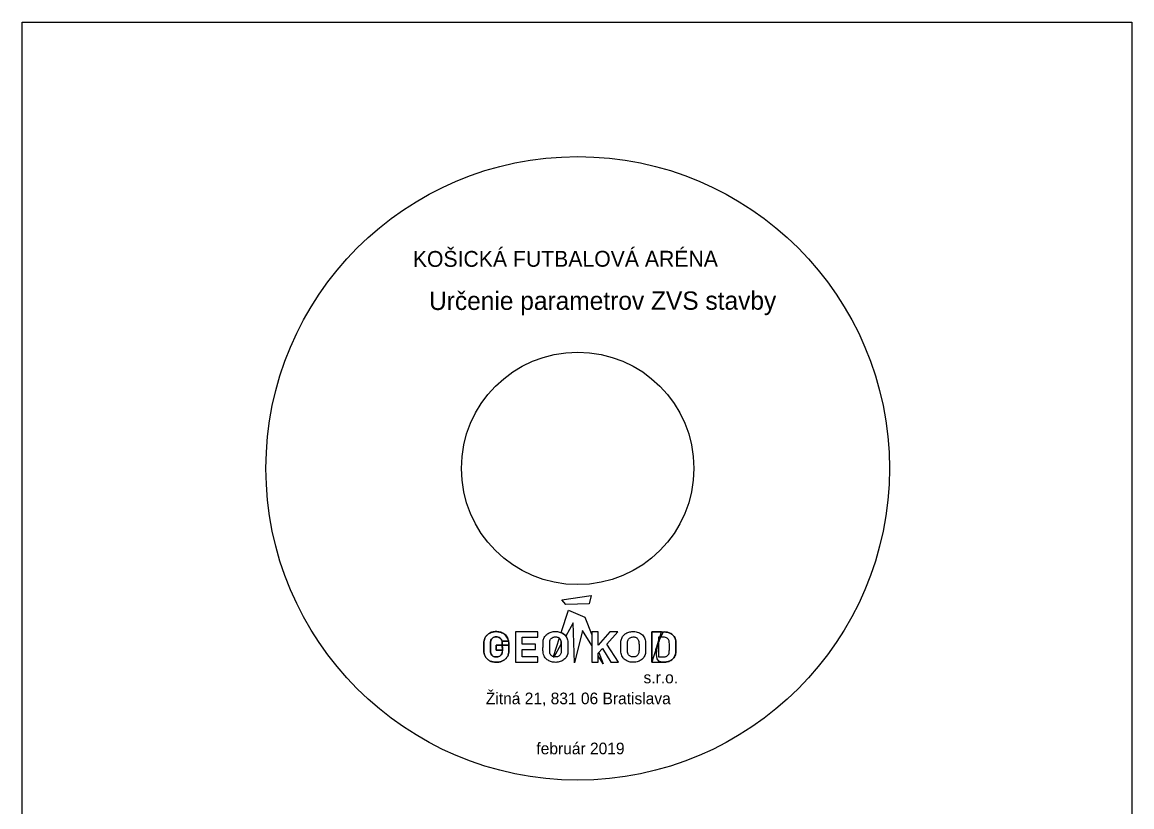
# Model space of a CAD drawing. Extents: x -505246 to -505036, y -1268489 to -1268192.
# Drawn here: x -505246.3 to -505036.3, y -1268340.7 to -1268192.2 of the extents above; entities that cross this region are included whole.
import ezdxf

# ---------------------------------------------------------------- set-up
doc = ezdxf.new("R2010")
doc.units = 0
for name, color, linetype in [('CD_KRUHY', 7, 'Continuous'), ('CD_POPIS', 7, 'Continuous'), ('RAM_NA_TLAC_A4', 7, 'Continuous')]:
    doc.layers.add(name, color=color, linetype=linetype)

msp = doc.modelspace()

# ---------------------------------------------------------------- linework, layer by layer
at = {"layer": 'CD_KRUHY'}
for radius in [59, 22]:
    msp.add_circle((-505141.22, -1268276.61), radius, dxfattribs=at)
at = {"layer": 'CD_POPIS'}
for p, q in [((-505144.36, -1268307.68), (-505142.96, -1268303.45)), ((-505142.96, -1268303.45), (-505139.85, -1268304.76)), ((-505139.85, -1268304.76), (-505138.54, -1268308.11)), ((-505145.5, -1268307.48), (-505145.4, -1268307.48)), ((-505142.07, -1268305.85), (-505143.47, -1268308.35)), ((-505141.8, -1268313.41), (-505142.07, -1268305.85)), ((-505140.31, -1268307.29), (-505141.8, -1268313.41)), ((-505138.54, -1268310.14), (-505140.31, -1268307.29)), ((-505137.32, -1268307.55), (-505138.54, -1268307.55)), ((-505135.12, -1268307.55), (-505137.32, -1268310.05)), ((-505137.32, -1268310.05), (-505137.32, -1268307.55)), ((-505135.7, -1268309.85), (-505133.6, -1268307.55)), ((-505133.6, -1268307.55), (-505135.12, -1268307.55)), ((-505127.18, -1268307.57), (-505125.35, -1268307.57)), ((-505127.18, -1268313.27), (-505127.18, -1268307.57)), ((-505127.18, -1268307.57), (-505127.18, -1268313.27)), ((-505125.35, -1268307.57), (-505127.18, -1268307.57)), ((-505154.25, -1268309.32), (-505155.51, -1268309.32)), ((-505155.51, -1268309.32), (-505154.25, -1268309.32)), ((-505144.71, -1268308.73), (-505145.87, -1268312.25)), ((-505145.48, -1268308.5), (-505145.41, -1268308.5)), ((-505145.48, -1268308.5), (-505145.41, -1268308.5)), ((-505138.54, -1268308.11), (-505138.54, -1268310.14)), ((-505125.93, -1268308.56), (-505125.93, -1268312.28)), ((-505125.93, -1268308.56), (-505125.93, -1268312.28)), ((-505137.22, -1268311.46), (-505136.37, -1268313.63)), ((-505133.49, -1268313.27), (-505135.7, -1268309.85)), ((-505136.37, -1268313.63), (-505137.32, -1268312.1)), ((-505134.93, -1268313.27), (-505133.49, -1268313.27))]:
    msp.add_line(p, q, dxfattribs=at)
for points in [[(-505144.2, -1268301.48), (-505138.67, -1268300.68), (-505139.06, -1268302.26), (-505143.47, -1268302.4)], [(-505152.99, -1268307.53), (-505152.99, -1268313.27), (-505148.78, -1268313.27), (-505148.78, -1268312.26), (-505151.73, -1268312.26), (-505151.73, -1268310.88), (-505149.21, -1268310.88), (-505149.21, -1268309.88), (-505151.73, -1268309.88), (-505151.73, -1268308.54), (-505148.78, -1268308.54), (-505148.78, -1268307.53)]]:
    msp.add_lwpolyline(points, close=True, dxfattribs=at)
for points in [[(-505138.54, -1268307.55), (-505138.54, -1268313.27), (-505137.32, -1268313.27), (-505137.32, -1268311.56), (-505136.51, -1268310.7), (-505134.93, -1268313.27)], [(-505144.33, -1268309.9), (-505144.33, -1268309.77), (-505144.34, -1268309.61), (-505144.35, -1268309.47), (-505144.37, -1268309.33), (-505144.41, -1268309.21), (-505144.46, -1268309.06), (-505144.53, -1268308.93), (-505144.62, -1268308.82), (-505144.71, -1268308.73)], [(-505143.47, -1268308.35), (-505143.51, -1268308.3), (-505143.58, -1268308.22), (-505143.65, -1268308.15), (-505143.74, -1268308.07), (-505143.82, -1268308), (-505143.91, -1268307.94), (-505143.99, -1268307.88), (-505144.08, -1268307.83), (-505144.18, -1268307.77), (-505144.27, -1268307.72), (-505144.36, -1268307.68)], [(-505155.47, -1268311.01), (-505156.67, -1268311.01), (-505156.67, -1268310.07), (-505154.23, -1268310.07)], [(-505154.23, -1268310.07), (-505156.67, -1268310.07), (-505156.67, -1268311.01), (-505155.47, -1268311.01)], [(-505145.68, -1268312.3), (-505144.33, -1268309.9)], [(-505137.32, -1268312.1), (-505137.32, -1268311.56), (-505137.22, -1268311.46)], [(-505145.87, -1268312.25), (-505145.84, -1268312.26), (-505145.8, -1268312.28), (-505145.77, -1268312.29), (-505145.73, -1268312.29), (-505145.7, -1268312.3), (-505145.68, -1268312.3)]]:
    msp.add_lwpolyline(points, dxfattribs=at)
for points in [[(-505154.23, -1268310.07), (-505154.23, -1268310.79), (-505154.25, -1268311.44), (-505154.38, -1268312.02), (-505154.66, -1268312.48), (-505155.08, -1268312.87), (-505155.53, -1268313.13), (-505156.12, -1268313.28), (-505156.66, -1268313.32), (-505157.22, -1268313.28), (-505157.78, -1268313.1), (-505158.26, -1268312.78), (-505158.63, -1268312.41), (-505158.88, -1268311.91), (-505158.99, -1268311.35), (-505159.01, -1268310.98), (-505159.01, -1268309.84), (-505158.97, -1268309.23), (-505158.8, -1268308.71), (-505158.52, -1268308.26), (-505157.97, -1268307.82), (-505157.37, -1268307.56), (-505156.68, -1268307.48), (-505155.96, -1268307.54), (-505155.19, -1268307.85), (-505154.6, -1268308.41), (-505154.25, -1268309.32), (-505154.23, -1268310.07), (-505154.25, -1268309.32)], [(-505154.25, -1268309.32), (-505154.6, -1268308.41), (-505155.19, -1268307.85), (-505155.96, -1268307.54), (-505156.68, -1268307.48), (-505157.37, -1268307.56), (-505157.97, -1268307.82), (-505158.52, -1268308.26), (-505158.8, -1268308.71), (-505158.97, -1268309.23), (-505159.01, -1268309.84), (-505159.01, -1268310.98), (-505158.99, -1268311.35), (-505158.88, -1268311.91), (-505158.63, -1268312.41), (-505158.26, -1268312.78), (-505157.78, -1268313.1), (-505157.22, -1268313.28), (-505156.66, -1268313.32), (-505156.12, -1268313.28), (-505155.53, -1268313.13), (-505155.08, -1268312.87), (-505154.66, -1268312.48), (-505154.38, -1268312.02), (-505154.25, -1268311.44), (-505154.23, -1268310.79), (-505154.23, -1268310.07), (-505154.25, -1268309.32), (-505154.23, -1268310.07)], [(-505145.4, -1268307.48), (-505145.37, -1268307.48), (-505145.2, -1268307.47), (-505144.88, -1268307.55), (-505144.45, -1268307.63), (-505144.04, -1268307.85), (-505143.67, -1268308.11), (-505143.37, -1268308.46), (-505143.19, -1268308.86), (-505143.08, -1268309.3), (-505143.08, -1268309.99), (-505143.06, -1268310.71), (-505143.08, -1268311.41), (-505143.14, -1268311.85), (-505143.31, -1268312.22), (-505143.52, -1268312.54), (-505143.81, -1268312.79), (-505144.12, -1268313.02), (-505144.5, -1268313.18), (-505144.92, -1268313.3), (-505145.38, -1268313.33), (-505145.81, -1268313.3), (-505146.19, -1268313.27), (-505146.51, -1268313.12), (-505146.82, -1268312.94), (-505147.12, -1268312.75), (-505147.39, -1268312.47), (-505147.6, -1268312.09), (-505147.75, -1268311.64), (-505147.82, -1268310.89), (-505147.75, -1268310.2), (-505147.79, -1268309.53), (-505147.73, -1268309.15), (-505147.64, -1268308.77), (-505147.46, -1268308.44), (-505147.22, -1268308.17), (-505146.96, -1268307.93), (-505146.63, -1268307.75), (-505146.26, -1268307.58), (-505145.87, -1268307.5), (-505145.61, -1268307.49), (-505145.5, -1268307.48)], [(-505130.68, -1268307.48), (-505131.11, -1268307.51), (-505131.56, -1268307.6), (-505131.93, -1268307.76), (-505132.23, -1268307.94), (-505132.5, -1268308.17), (-505132.72, -1268308.44), (-505132.91, -1268308.78), (-505133.01, -1268309.15), (-505133.06, -1268309.51), (-505133.05, -1268309.92), (-505133.07, -1268311.15), (-505133.02, -1268311.61), (-505132.85, -1268312.12), (-505132.64, -1268312.48), (-505132.41, -1268312.72), (-505132.09, -1268312.95), (-505131.79, -1268313.11), (-505131.48, -1268313.24), (-505131.1, -1268313.3), (-505130.69, -1268313.32), (-505130.2, -1268313.28), (-505129.76, -1268313.16), (-505129.42, -1268313.01), (-505129.08, -1268312.78), (-505128.81, -1268312.53), (-505128.61, -1268312.23), (-505128.44, -1268311.84), (-505128.37, -1268311.44), (-505128.35, -1268310.94), (-505128.36, -1268309.75), (-505128.38, -1268309.29), (-505128.48, -1268308.88), (-505128.68, -1268308.46), (-505128.94, -1268308.14), (-505129.35, -1268307.84), (-505129.73, -1268307.65), (-505130.17, -1268307.54), (-505130.6, -1268307.48), (-505130.68, -1268307.48), (-505130.68, -1268307.48), (-505130.68, -1268307.48)], [(-505125.35, -1268307.57), (-505124.76, -1268307.57), (-505124.39, -1268307.59), (-505124.11, -1268307.64), (-505123.76, -1268307.77), (-505123.42, -1268307.96), (-505123.08, -1268308.27), (-505122.83, -1268308.63), (-505122.71, -1268308.97), (-505122.63, -1268309.5), (-505122.63, -1268309.76), (-505122.62, -1268310.89), (-505122.64, -1268311.27), (-505122.67, -1268311.57), (-505122.72, -1268311.89), (-505122.88, -1268312.29), (-505123.17, -1268312.66), (-505123.59, -1268312.99), (-505123.93, -1268313.14), (-505124.28, -1268313.24), (-505124.57, -1268313.27), (-505124.68, -1268313.27), (-505127.18, -1268313.27), (-505125.35, -1268307.57), (-505127.18, -1268313.27)], [(-505127.18, -1268313.27), (-505124.68, -1268313.27), (-505124.57, -1268313.27), (-505124.28, -1268313.24), (-505123.93, -1268313.14), (-505123.59, -1268312.99), (-505123.17, -1268312.66), (-505122.88, -1268312.29), (-505122.72, -1268311.89), (-505122.67, -1268311.57), (-505122.64, -1268311.27), (-505122.62, -1268310.89), (-505122.63, -1268309.76), (-505122.63, -1268309.5), (-505122.71, -1268308.97), (-505122.83, -1268308.63), (-505123.08, -1268308.27), (-505123.42, -1268307.96), (-505123.76, -1268307.77), (-505124.11, -1268307.64), (-505124.39, -1268307.59), (-505124.76, -1268307.57), (-505125.35, -1268307.57), (-505127.18, -1268313.27), (-505125.35, -1268307.57)], [(-505155.5, -1268309.32), (-505155.63, -1268309.01), (-505155.9, -1268308.7), (-505156.29, -1268308.53), (-505156.67, -1268308.5), (-505157.05, -1268308.54), (-505157.35, -1268308.72), (-505157.58, -1268308.96), (-505157.69, -1268309.22), (-505157.7, -1268309.61), (-505157.73, -1268310.04), (-505157.74, -1268310.55), (-505157.73, -1268311.16), (-505157.68, -1268311.6), (-505157.51, -1268311.96), (-505157.27, -1268312.16), (-505156.98, -1268312.28), (-505156.68, -1268312.32), (-505156.31, -1268312.3), (-505155.93, -1268312.14), (-505155.66, -1268311.88), (-505155.5, -1268311.58), (-505155.47, -1268311.24), (-505155.47, -1268311.01), (-505155.5, -1268309.32), (-505155.47, -1268311.01)], [(-505155.47, -1268311.01), (-505155.47, -1268311.24), (-505155.5, -1268311.58), (-505155.66, -1268311.88), (-505155.93, -1268312.14), (-505156.31, -1268312.3), (-505156.68, -1268312.32), (-505156.98, -1268312.28), (-505157.27, -1268312.16), (-505157.51, -1268311.96), (-505157.68, -1268311.6), (-505157.73, -1268311.16), (-505157.74, -1268310.55), (-505157.73, -1268310.04), (-505157.7, -1268309.61), (-505157.69, -1268309.22), (-505157.58, -1268308.96), (-505157.35, -1268308.72), (-505157.05, -1268308.54), (-505156.67, -1268308.5), (-505156.29, -1268308.53), (-505155.9, -1268308.7), (-505155.63, -1268309.01), (-505155.5, -1268309.32), (-505155.47, -1268311.01), (-505155.5, -1268309.32)], [(-505145.41, -1268308.5), (-505145.36, -1268308.5), (-505145.23, -1268308.5), (-505145, -1268308.55), (-505144.75, -1268308.68), (-505144.52, -1268308.9), (-505144.38, -1268309.22), (-505144.32, -1268309.57), (-505144.33, -1268309.96), (-505144.32, -1268310.37), (-505144.34, -1268310.79), (-505144.32, -1268311.18), (-505144.37, -1268311.51), (-505144.45, -1268311.8), (-505144.63, -1268312.06), (-505144.91, -1268312.24), (-505145.2, -1268312.32), (-505145.44, -1268312.3), (-505145.65, -1268312.32), (-505145.88, -1268312.26), (-505146.11, -1268312.12), (-505146.33, -1268311.91), (-505146.48, -1268311.6), (-505146.53, -1268311.23), (-505146.51, -1268310.78), (-505146.52, -1268310.27), (-505146.51, -1268309.79), (-505146.5, -1268309.39), (-505146.43, -1268309.08), (-505146.26, -1268308.83), (-505146.03, -1268308.64), (-505145.75, -1268308.52), (-505145.56, -1268308.5), (-505145.48, -1268308.5)], [(-505145.41, -1268308.5), (-505145.36, -1268308.5), (-505145.23, -1268308.5), (-505145, -1268308.55), (-505144.75, -1268308.68), (-505144.52, -1268308.9), (-505144.38, -1268309.22), (-505144.32, -1268309.57), (-505144.33, -1268309.96), (-505144.32, -1268310.37), (-505144.34, -1268310.79), (-505144.32, -1268311.18), (-505144.37, -1268311.51), (-505144.45, -1268311.8), (-505144.63, -1268312.06), (-505144.91, -1268312.24), (-505145.2, -1268312.32), (-505145.44, -1268312.3), (-505145.65, -1268312.32), (-505145.88, -1268312.26), (-505146.11, -1268312.12), (-505146.33, -1268311.91), (-505146.48, -1268311.6), (-505146.53, -1268311.23), (-505146.51, -1268310.78), (-505146.52, -1268310.27), (-505146.51, -1268309.79), (-505146.5, -1268309.39), (-505146.43, -1268309.08), (-505146.26, -1268308.83), (-505146.03, -1268308.64), (-505145.75, -1268308.52), (-505145.56, -1268308.5), (-505145.48, -1268308.5)], [(-505130.7, -1268308.5), (-505131, -1268308.53), (-505131.31, -1268308.65), (-505131.54, -1268308.85), (-505131.69, -1268309.07), (-505131.77, -1268309.39), (-505131.79, -1268309.73), (-505131.8, -1268310.25), (-505131.8, -1268310.84), (-505131.8, -1268311.24), (-505131.74, -1268311.6), (-505131.58, -1268311.92), (-505131.38, -1268312.12), (-505131.16, -1268312.25), (-505130.92, -1268312.31), (-505130.72, -1268312.31), (-505130.52, -1268312.31), (-505130.21, -1268312.23), (-505129.91, -1268312.02), (-505129.75, -1268311.8), (-505129.66, -1268311.52), (-505129.61, -1268311.19), (-505129.61, -1268310.82), (-505129.61, -1268310.36), (-505129.61, -1268309.94), (-505129.62, -1268309.6), (-505129.69, -1268309.19), (-505129.82, -1268308.92), (-505130.04, -1268308.69), (-505130.31, -1268308.56), (-505130.53, -1268308.51), (-505130.7, -1268308.5), (-505130.7, -1268308.5), (-505130.7, -1268308.5)], [(-505125.93, -1268312.28), (-505125.57, -1268312.28), (-505125.19, -1268312.28), (-505124.79, -1268312.28), (-505124.72, -1268312.28), (-505124.57, -1268312.25), (-505124.34, -1268312.14), (-505124.05, -1268311.93), (-505123.91, -1268311.58), (-505123.87, -1268311.2), (-505123.87, -1268310.66), (-505123.87, -1268310.05), (-505123.87, -1268309.55), (-505123.9, -1268309.21), (-505124.03, -1268308.98), (-505124.29, -1268308.74), (-505124.57, -1268308.61), (-505124.96, -1268308.56), (-505125.23, -1268308.56), (-505125.76, -1268308.56), (-505125.93, -1268308.56)], [(-505125.93, -1268312.28), (-505125.57, -1268312.28), (-505125.19, -1268312.28), (-505124.79, -1268312.28), (-505124.72, -1268312.28), (-505124.57, -1268312.25), (-505124.34, -1268312.14), (-505124.05, -1268311.93), (-505123.91, -1268311.58), (-505123.87, -1268311.2), (-505123.87, -1268310.66), (-505123.87, -1268310.05), (-505123.87, -1268309.55), (-505123.9, -1268309.21), (-505124.03, -1268308.98), (-505124.29, -1268308.74), (-505124.57, -1268308.61), (-505124.96, -1268308.56), (-505125.23, -1268308.56), (-505125.76, -1268308.56), (-505125.93, -1268308.56)]]:
    msp.add_open_spline(points, degree=3, dxfattribs=at)
at = {"layer": 'RAM_NA_TLAC_A4'}
for p, q in [((-505246.35, -1268489.16), (-505246.35, -1268192.16)), ((-505246.35, -1268192.16), (-505036.35, -1268192.16)), ((-505036.35, -1268192.16), (-505036.35, -1268489.16))]:
    msp.add_line(p, q, dxfattribs=at)

# ---------------------------------------------------------------- texts
at = {"layer": 'CD_POPIS'}
for s, height, rotation, p in [('KOŠICKÁ FUTBALOVÁ ARÉNA', 3, 0.0456, (-505172.42, -1268238.47)), ('Určenie parametrov ZVS stavby', 3.4676, 0.0456, (-505169.35, -1268246.63)), ('s.r.o.', 2.2, 0.0016, (-505128.76, -1268317.29)), ('Žitná 21, 831 06 Bratislava', 2.2, 0.0016, (-505158.6, -1268321.25)), ('február 2019', 2.2, 0.0016, (-505149.03, -1268330.72))]:
    msp.add_text(s, height=height, rotation=rotation, dxfattribs=at).set_placement(p)

doc.saveas('drawing.dxf')
